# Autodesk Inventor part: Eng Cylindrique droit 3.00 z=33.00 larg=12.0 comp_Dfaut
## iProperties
Created: 2007-07
Part Number: Eng Cylindrique droit 3.00 z=33.00 larg=12.0 comp_Dfaut
Document SubType Name: Modeling
Designer: EF
Density: 1 g/cm^3
Author: EF
